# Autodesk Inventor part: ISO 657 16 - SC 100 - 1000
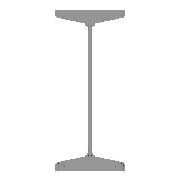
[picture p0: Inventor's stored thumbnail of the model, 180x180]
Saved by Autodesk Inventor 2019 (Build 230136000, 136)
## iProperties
_CCFamilyMember: 1
_CCFamilyDisplayName: ISO 657/16 - 1980 - Poutres en acier laminées à chaud - Partie 16: profilés en H (série métrique) - Cotes et propriétés de section
_FrameMemberDoc: Frame Member File
_Version: 15.0.0
_GetPNFromCC: 1
Created: 2018-07
Part Number: ISO 657 16 - SC 100 - 1000
Material: Acier, doux
Description: Poutres en acier laminées à chaud - Partie 16: profilés en H (série métrique) - Cotes et propriétés de section
Document SubType Name: Modeling
Standard: ISO
Designer: Fabian Perrée
Standard Revision: First edition 1980-02-15
Standards Organization: ISO
Language: fr-FR
Size Designation: SC 100
Categories: <MemberInstance><Categories><Category DisplayName="Profilés" InternalName="089c4875-fa83-4c05-b084-43b9cc11f5ed" Mnemonic="GRDR"><CategoryParameter DisplayName=
Stock Number: SC 100
Density: 7.85 g/cm^3
Appearance: Semi-poli
Mass: 18568.7 g
Surface Area: 5212.93 cm^2
Volume: 2365.44 cm^3
IsCustomPart: 1
G_W: 100,000 mm
G_H: 100,000 mm
G_L: 1000,000 mm
+0FF60940-F4FF-4C86-8406-4262D265074C+DETAILDECOUPE7: Grugeage
+041294D9-D90F-4F3A-86FE-30375D234781+DETAILDECOUPE8: Grugeage
Author: Fabian Perrée
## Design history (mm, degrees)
node "Plan de départ"
node "Plan de fin"
sketch "Esquisse"
  geometry: L1 (-3, 0)-(-3, -26.266); L2 (-13.33, -38.149)-(-44.835, -42.577); L3 (-50, -48.518)-(-50, -50); L4 (-50, -50)-(0, -50); L5 (-26.5, -50)-(-26.5, -40); L6 (-61.333, 0)-(81.777, 0); L7 (0, 0)-(0, -50); L8 (0, -60)-(0, 80); L9 (3, 0)-(3, -26.266); L10 (13.33, -38.149)-(44.835, -42.577); L11 (50, -48.518)-(50, -50); L12 (50, -50)-(0, -50); L13 (-3, 0)-(0, 0); L14 (-3, 0)-(-3, 26.266); L15 (-13.33, 38.149)-(-44.835, 42.577); L16 (-50, 48.518)-(-50, 50); L17 (-50, 50)-(0, 50); L18 (50, 48.518)-(50, 50); L19 (13.33, 38.149)-(44.835, 42.577); L20 (3, 0)-(3, 26.266); L21 (50, 50)-(0, 50); L22 (0, 108)-(0, -88) reference; L23 (-89.955, 0)-(110.399, 0) reference; A1 r 6 centre (-44, 48.518) between (-50, 48.518) and (-44.835, 42.577); A2 r 6 centre (44, 48.518) between (44.835, 42.577) and (50, 48.518); A3 r 6 centre (44, -48.518) between (50, -48.518) and (44.835, -42.577); A4 r 6 centre (-44, -48.518) between (-44.835, -42.577) and (-50, -48.518); A5 r 12 centre (-15, 26.266) between (-3, 26.266) and (-13.33, 38.149); A6 r 12 centre (15, 26.266) between (13.33, 38.149) and (3, 26.266); A7 r 12 centre (15, -26.266) between (3, -26.266) and (13.33, -38.149); A8 r 12 centre (-15, -26.266) between (-13.33, -38.149) and (-3, -26.266); 14 further points
  constraints: 42 end point, 24 point on line, 17 symmetric about line, 16 point on circle, 16 tangent, 8 centre point, 6 equal radius, 4 collinear, 2 perpendicular, 12 other
  dimensions: "d1" = 10 vertical distance of L3.end L5.end (= G_T1); "d2" = 23.5 distance between parallel lines of L5 L3 (= -0.25 x G_T + 0.25 x G_W); "d3" = 3 distance between parallel lines of L1 L7 (= 0.5 x G_T); "d4" = 50 distance between parallel lines of L7 L3 (= 0.5 x G_W); "d9" = 50 distance from line of L1.start L4 (= 0.5 x G_H); "d14" = 98 deg angle of L2 L1 (= G_NG); "d15" = 6 radius of A1 (= G_ER); "d16" = 12 radius of A5 (= G_IR)
extrude "Corps" new body sketch "Esquisse" stored distance "d5" = 1000 (= G_L); taper "d6" = 0 deg
node "Driven Length"
  sketch "Sketch3"
    geometry: L1 (0, 0)-(10, 0) reference
    constraints: 2 end point, 1 horizontal
  workplane "Work Plane3"
  sketch "Sketch4"
    geometry: L1 (-2, 0)-(12, 0) reference; L2 (-2, 1000)-(12, 1000) reference
    dimensions: "d20" = 1000 distance between parallel lines of L1 L2 (derived)
node "Plan de construction12"
node "Plan de construction13"
node "Plan de construction14"
sketch "Esquisse5"
  geometry: L1 (-3, 0)-(-3, -26.266); L2 (-13.33, -38.149)-(-44.835, -42.577); L3 (-50, -48.518)-(-50, -50); L4 (-50, -50)-(0, -50); L5 (50, -50)-(0, -50); L6 (50, -48.518)-(50, -50); L7 (13.33, -38.149)-(44.835, -42.577); L8 (3, 0)-(3, -26.266); L9 (3, 0)-(3, 26.266); L10 (13.33, 38.149)-(44.835, 42.577); L11 (50, 48.518)-(50, 50); L12 (50, 50)-(0, 50); L13 (-50, 50)-(0, 50); L14 (-50, 48.518)-(-50, 50); L15 (-13.33, 38.149)-(-44.835, 42.577); L16 (-3, 0)-(-3, 26.266); A1 r 12 centre (-15, -26.266) between (-13.33, -38.149) and (-3, -26.266); A2 r 6 centre (-44, -48.518) between (-44.835, -42.577) and (-50, -48.518); A3 r 6 centre (44, -48.518) between (50, -48.518) and (44.835, -42.577); A4 r 12 centre (15, -26.266) between (3, -26.266) and (13.33, -38.149); A5 r 12 centre (15, 26.266) between (13.33, 38.149) and (3, 26.266); A6 r 6 centre (44, 48.518) between (44.835, 42.577) and (50, 48.518); A7 r 6 centre (-44, 48.518) between (-50, 48.518) and (-44.835, 42.577); A8 r 12 centre (-15, 26.266) between (-3, 26.266) and (-13.33, 38.149)
  constraints: 32 end point, 16 point on circle, 8 centre point
extrude "Extrusion2" cut sketch "Esquisse5" stored distance "d21" = 0.13; taper "d22" = 0 deg
node "Plan de construction15"
node "Plan de construction16"
node "Plan de construction17"
sketch "Esquisse6"
  geometry: L1 (-3, 0)-(-3, -26.266); L2 (-13.33, -38.149)-(-44.835, -42.577); L3 (-50, -48.518)-(-50, -50); L4 (-50, -50)-(0, -50); L5 (50, -50)-(0, -50); L6 (50, -48.518)-(50, -50); L7 (13.33, -38.149)-(44.835, -42.577); L8 (3, 0)-(3, -26.266); L9 (3, 0)-(3, 26.266); L10 (13.33, 38.149)-(44.835, 42.577); L11 (50, 48.518)-(50, 50); L12 (50, 50)-(0, 50); L13 (-50, 50)-(0, 50); L14 (-50, 48.518)-(-50, 50); L15 (-13.33, 38.149)-(-44.835, 42.577); L16 (-3, 0)-(-3, 26.266); A1 r 12 centre (-15, -26.266) between (-13.33, -38.149) and (-3, -26.266); A2 r 6 centre (-44, -48.518) between (-44.835, -42.577) and (-50, -48.518); A3 r 6 centre (44, -48.518) between (50, -48.518) and (44.835, -42.577); A4 r 12 centre (15, -26.266) between (3, -26.266) and (13.33, -38.149); A5 r 12 centre (15, 26.266) between (13.33, 38.149) and (3, 26.266); A6 r 6 centre (44, 48.518) between (44.835, 42.577) and (50, 48.518); A7 r 6 centre (-44, 48.518) between (-50, 48.518) and (-44.835, 42.577); A8 r 12 centre (-15, 26.266) between (-3, 26.266) and (-13.33, 38.149)
  constraints: 32 end point, 16 point on circle, 8 centre point
extrude "Extrusion3" cut sketch "Esquisse6" stored distance "d23" = 0.13; taper "d24" = 0 deg
body "Solid1"
other parameters: "G_W" = 100 (= G_H) [user parameter; used in 2 equation terms], "G_H" = 100 [user parameter; used in 2 equation terms], "G_T" = 6 [user parameter; used in 2 equation terms], "G_T1" = 10 [user parameter; used in 1 equation term], "G_L" = 1000 (= d20) [user parameter; used in 1 equation term], "G_ER" = 6 [user parameter; used in 1 equation term], "G_IR" = 12 [user parameter; used in 1 equation term], "G_NG" = 98 deg [user parameter; used in 1 equation term], "G_OFFSET_START" = 0 [user parameter; used in 1 equation term], "G_OFFSET_END" = 0 [user parameter; used in 1 equation term], "d17" = 0 (computed from G_OFFSET_START), "d19" = 90 deg
